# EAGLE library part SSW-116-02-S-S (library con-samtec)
THROUGH-HOLE .025" SQ POST SOCKET Source: Samtec SSW.pdf
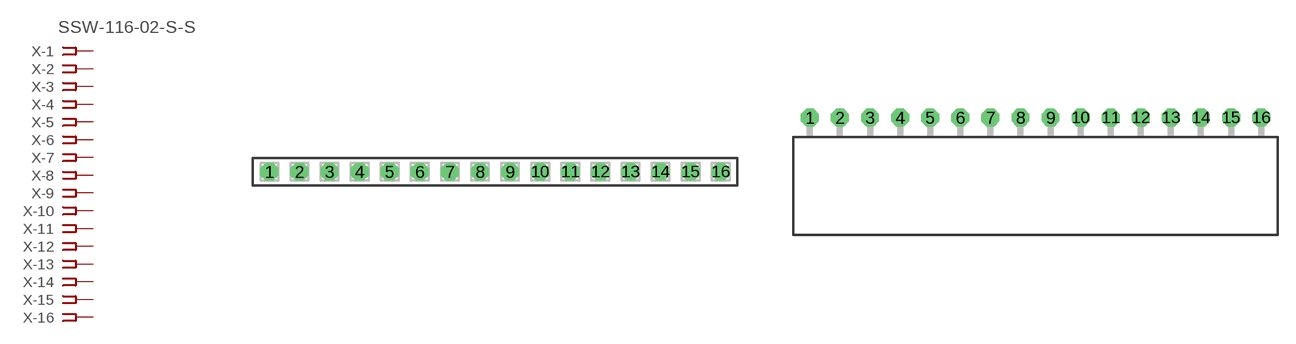
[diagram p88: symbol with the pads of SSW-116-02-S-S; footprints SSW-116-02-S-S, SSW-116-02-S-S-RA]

Designator prefix X; gates -1=FPINV -2=FPIN -3=FPIN -4=FPIN -5=FPIN -6=FPIN -7=FPIN -8=FPIN -9=FPIN -10=FPIN -11=FPIN -12=FPIN -13=FPIN -14=FPIN -15=FPIN -16=FPIN

## SSW-116-02-S-S (MPN: SSW-116-02-S-S; OC_FARNELL: unknown; OC_NEWARK: 29C5896)  [SSW-116-02-S-S]
1  -1:1  pas
2  -2:1  pas
3  -3:1  pas
4  -4:1  pas
5  -5:1  pas
6  -6:1  pas
7  -7:1  pas
8  -8:1  pas
9  -9:1  pas
10  -10:1  pas
11  -11:1  pas
12  -12:1  pas
13  -13:1  pas
14  -14:1  pas
15  -15:1  pas
16  -16:1  pas

## SSW-116-02-S-S-RA (MPN: SSW-116-02-S-S-RA; OC_FARNELL: unknown; OC_NEWARK: 11P9579)  [SSW-116-02-S-S-RA]
Pads as for SSW-116-02-S-S

## Footprint SSW-116-02-S-S (pad centres in mm)
THROUGH-HOLE .025" SQ POST SOCKET Source: Samtec SSW.pdf
drill 1 pad 1.5 octagon: 1 -19.05,0; 2 -16.51,0; 3 -13.97,0; 4 -11.43,0; 5 -8.89,0; 6 -6.35,0; 7 -3.81,0; 8 -1.27,0; 9 1.27,0; 10 3.81,0; 11 6.35,0; 12 8.89,0; 13 11.43,0; 14 13.97,0; 15 16.51,0; 16 19.05,0

## Footprint SSW-116-02-S-S-RA (pad centres in mm)
THROUGH-HOLE .025" SQ POST SOCKET Source: Samtec SSW.pdf
drill 1 pad 1.5 octagon: 1 -19.05,1.524; 2 -16.51,1.524; 3 -13.97,1.524; 4 -11.43,1.524; 5 -8.89,1.524; 6 -6.35,1.524; 7 -3.81,1.524; 8 -1.27,1.524; 9 1.27,1.524; 10 3.81,1.524; 11 6.35,1.524; 12 8.89,1.524; 13 11.43,1.524; 14 13.97,1.524; 15 16.51,1.524; 16 19.05,1.524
